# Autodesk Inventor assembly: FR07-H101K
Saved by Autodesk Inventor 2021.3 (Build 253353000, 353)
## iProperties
Created: 2022-04
Part Number: FR07-H101K
Document SubType Name: Assembly
Designer: Administrator
Title: FR07-H101K v5
Author: Administrator
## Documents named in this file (2)
- c:\worker\convert-fusion-r02\tmp\job-1\57\output\files\f9e42cba-e390-44b0-9630-f24d5638462a\FR07-H101K v5.iam
- c:\worker\convert-fusion-r02\tmp\job-1\57\output\files\f9e42cba-e390-44b0-9630-f24d5638462a\Component1.ipt
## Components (1 placed, 1 different names)
1. Component1:1
